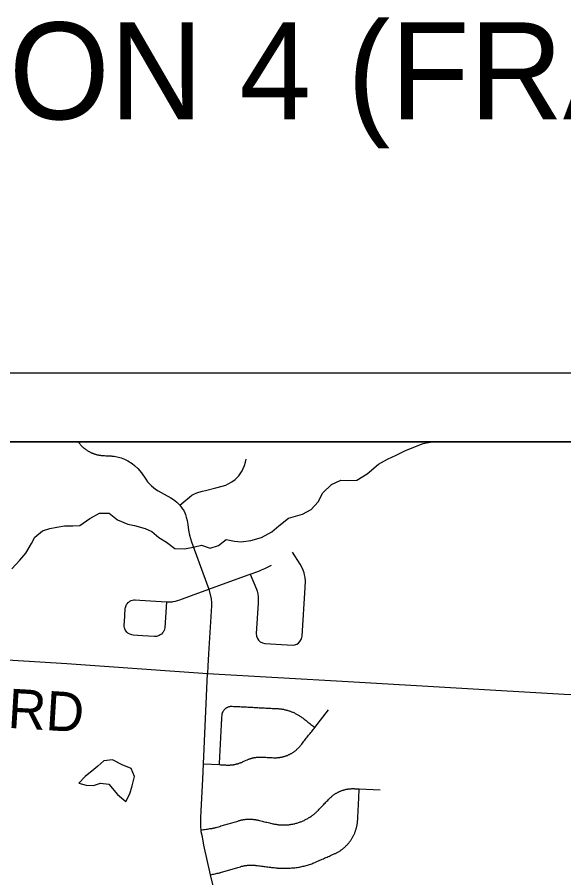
# Model space of a CAD drawing. Extents: x 0 to 34, y 0 to 22.
# Drawn here: x 6.189 to 6.979, y 9.554 to 10.798 of the extents above; entities that cross this region are included whole.
import ezdxf

# ---------------------------------------------------------------- set-up
doc = ezdxf.new("R2010")
doc.units = 0
for name, color, linetype in [('Default', 7, 'Continuous'), ('GM_X_Corporation', 7, 'Continuous'), ('GM_X_Minor_Lake', 7, 'Continuous'), ('GM_X_Minor_River', 7, 'Continuous'), ('GM_X_Township_Road', 7, 'Continuous'), ('GM_X_Township_Road_Text', 7, 'Continuous'), ('SH_Data', 7, 'Continuous')]:
    doc.layers.add(name, color=color, linetype=linetype)

msp = doc.modelspace()

# ---------------------------------------------------------------- linework, layer by layer
at = {"layer": 'GM_X_Corporation'}
for points in [[(10.3182, 6.9963), (10.3182, 10.1841), (3.5182, 10.1841)], [(7.8118, 7.1421), (7.8248, 7.359), (7.8619, 7.9568), (7.8769, 8.1664), (7.8824, 8.2446), (7.9043, 8.6471), (7.9173, 8.8475), (7.9854, 9.7171), (7.9906, 9.8037), (8.012, 10.1113), (8.0168, 10.1841), (3.5182, 10.1841)]]:
    msp.add_lwpolyline(points, dxfattribs=at)
at = {"layer": 'GM_X_Minor_Lake'}
for points in [[(6.3051, 9.7156), (6.2995, 9.7106), (6.287, 9.7007), (6.2776, 9.6908), (6.2882, 9.6882), (6.2988, 9.6874), (6.309, 9.6909), (6.3211, 9.6897), (6.3336, 9.6746), (6.3457, 9.6644)], [(6.3457, 9.6644), (6.3518, 9.6754), (6.3548, 9.6871), (6.3585, 9.7004), (6.3536, 9.7122), (6.3404, 9.7174), (6.3264, 9.7246), (6.3139, 9.7235), (6.3051, 9.7156)]]:
    msp.add_lwpolyline(points, dxfattribs=at)
at = {"layer": 'GM_X_Minor_River'}
msp.add_lwpolyline([(6.1808, 10.0008), (6.1925, 10.0133), (6.2012, 10.0236), (6.2095, 10.0372), (6.214, 10.0467), (6.2253, 10.0558), (6.2359, 10.0592), (6.2462, 10.0612), (6.2571, 10.0627), (6.2692, 10.0627), (6.2791, 10.0635), (6.2938, 10.0734), (6.3078, 10.0813), (6.3218, 10.081), (6.3339, 10.0715), (6.3487, 10.0651), (6.3585, 10.0632), (6.3737, 10.0591), (6.3835, 10.0546), (6.3934, 10.0462), (6.4047, 10.0394), (6.4168, 10.0303), (6.4305, 10.0296), (6.4433, 10.0323), (6.4551, 10.0349), (6.4679, 10.0304), (6.4797, 10.0346), (6.4906, 10.0433), (6.5027, 10.0407), (6.5126, 10.0396), (6.5266, 10.0419), (6.5417, 10.0461), (6.5568, 10.0541), (6.567, 10.0628), (6.5807, 10.0738), (6.5912, 10.0769), (6.6011, 10.0799), (6.6136, 10.0864), (6.6238, 10.0978), (6.6306, 10.1107), (6.643, 10.1228), (6.6566, 10.1289), (6.6676, 10.1285), (6.6797, 10.1289), (6.6945, 10.138), (6.7111, 10.1521), (6.724, 10.1593), (6.7365, 10.165), (6.7493, 10.1715), (6.7622, 10.1768), (6.7758, 10.1821), (6.7879, 10.1841), (6.7881, 10.1841)], dxfattribs=at)
at = {"layer": 'GM_X_Township_Road'}
for points in [[(6.2776, 10.1832), (6.2781, 10.1825), (6.2786, 10.1819), (6.2791, 10.1813), (6.2796, 10.1807), (6.2802, 10.1801), (6.2807, 10.1795), (6.2813, 10.1789), (6.2818, 10.1783), (6.2824, 10.1777), (6.283, 10.1772), (6.2836, 10.1766), (6.2842, 10.1761), (6.2848, 10.1755), (6.2855, 10.175), (6.2861, 10.1745), (6.2868, 10.174), (6.2874, 10.1735), (6.2881, 10.1731), (6.2887, 10.1726), (6.2894, 10.1721), (6.2901, 10.1717), (6.2908, 10.1713), (6.2915, 10.1709), (6.2922, 10.1705), (6.2929, 10.1701), (6.2936, 10.1697), (6.2944, 10.1693), (6.2951, 10.169), (6.2958, 10.1686), (6.2966, 10.1683), (6.2973, 10.168), (6.2981, 10.1677), (6.2988, 10.1674), (6.2996, 10.1671), (6.3004, 10.1668), (6.3011, 10.1666), (6.3019, 10.1664), (6.3027, 10.1661), (6.3035, 10.1659), (6.3043, 10.1657), (6.3051, 10.1655), (6.3059, 10.1654), (6.3067, 10.1652), (6.3075, 10.1651), (6.3083, 10.165), (6.3091, 10.1648), (6.3099, 10.1647), (6.3107, 10.1647), (6.3115, 10.1646), (6.3123, 10.1645), (6.3131, 10.1645), (6.315, 10.1644), (6.3169, 10.1643), (6.3188, 10.1642), (6.3207, 10.1641), (6.3226, 10.164), (6.3236, 10.164), (6.3246, 10.1639), (6.3256, 10.1638), (6.3267, 10.1637), (6.3277, 10.1636), (6.3288, 10.1634), (6.335, 10.1622), (6.3391, 10.161), (6.344, 10.1591), (6.3487, 10.1567), (6.355, 10.1528), (6.3584, 10.1502), (6.3631, 10.146), (6.3685, 10.1395), (6.3746, 10.1305), (6.3772, 10.1267), (6.3828, 10.1205), (6.3886, 10.1159), (6.3923, 10.1136), (6.4014, 10.1086), (6.4106, 10.1036), (6.4146, 10.1011), (6.4195, 10.0973), (6.4238, 10.0928), (6.4273, 10.0881), (6.4299, 10.0841), (6.4319, 10.0792), (6.4332, 10.0753), (6.4344, 10.0705), (6.4352, 10.065), (6.4363, 10.0566), (6.4376, 10.0495), (6.4406, 10.0397), (6.4517, 10.0094), (6.4657, 9.9712), (6.469, 9.9573), (6.4694, 9.9517), (6.4694, 9.9472), (6.4651, 9.8777), (6.4641, 9.8603), (6.4639, 9.8496)], [(6.4238, 10.0928), (6.4295, 10.0978), (6.4376, 10.1045), (6.4414, 10.1071), (6.4443, 10.1087), (6.4484, 10.1106), (6.4515, 10.1117), (6.4568, 10.1132), (6.461, 10.1142), (6.4758, 10.1179), (6.4849, 10.1201), (6.4904, 10.1219), (6.4938, 10.1235), (6.4988, 10.1263), (6.5037, 10.1301), (6.5089, 10.1354), (6.511, 10.138), (6.5139, 10.1425), (6.5156, 10.1458), (6.5173, 10.15), (6.5188, 10.1551), (6.5196, 10.1592)], [(6.5256, 9.993), (6.5345, 9.9714), (6.5354, 9.9684), (6.5364, 9.9644), (6.5371, 9.9597), (6.5371, 9.9509), (6.5343, 9.9072), (6.5346, 9.9036), (6.5359, 9.9002), (6.5375, 9.8978), (6.5402, 9.8953), (6.5431, 9.8936), (6.5468, 9.8927), (6.5872, 9.8902), (6.5902, 9.8907), (6.5928, 9.8917), (6.5955, 9.8935), (6.5974, 9.8956), (6.5997, 9.8996), (6.6005, 9.9034), (6.605, 9.9737), (6.6054, 9.9829), (6.6049, 9.9883), (6.6041, 9.9923), (6.6034, 9.9951), (6.6022, 9.9986), (6.6007, 10.002), (6.5976, 10.0075), (6.5866, 10.0247)], [(6.4044, 9.9531), (6.4029, 9.9304), (6.4022, 9.9154), (6.4017, 9.9136), (6.4011, 9.9118), (6.4006, 9.911), (6.3997, 9.9093), (6.3988, 9.9081), (6.3972, 9.9065), (6.3954, 9.9052), (6.3941, 9.9044), (6.3928, 9.9038), (6.3916, 9.9035), (6.3901, 9.9031), (6.3887, 9.903), (6.3872, 9.9029), (6.3699, 9.9041), (6.3566, 9.9048), (6.3545, 9.9053), (6.3528, 9.9057), (6.3508, 9.9067), (6.3487, 9.908), (6.3473, 9.9094), (6.3461, 9.9107), (6.345, 9.9126), (6.3444, 9.914), (6.3438, 9.9156), (6.3435, 9.9173), (6.3434, 9.9198), (6.3437, 9.9244), (6.345, 9.943), (6.345, 9.9439), (6.3453, 9.9451), (6.3462, 9.9477), (6.3468, 9.949), (6.3477, 9.9503), (6.3491, 9.9519), (6.3501, 9.9528), (6.3515, 9.9538), (6.3534, 9.9548), (6.3556, 9.9556), (6.3575, 9.9559), (6.3592, 9.956), (6.3661, 9.9556), (6.3968, 9.9536), (6.4044, 9.9531), (6.4093, 9.953), (6.4126, 9.9533), (6.4143, 9.9535), (6.4176, 9.9541), (6.4207, 9.9549), (6.4236, 9.9558), (6.4407, 9.9621), (6.4657, 9.9712), (6.5225, 9.9919), (6.5256, 9.993), (6.5379, 9.9975), (6.542, 9.9991), (6.5445, 10.0001), (6.5469, 10.0012), (6.5517, 10.0035), (6.5565, 10.006)], [(5.4689, 9.9123), (5.5957, 9.9046), (5.9632, 9.8822), (6.2604, 9.864), (6.4639, 9.8496), (6.6673, 9.838), (6.9796, 9.8194), (7.0349, 9.8181)], [(6.4798, 9.5107), (6.4683, 9.5585), (6.4585, 9.6014), (6.4564, 9.6135), (6.4548, 9.6205), (6.4545, 9.6233), (6.454, 9.6278), (6.454, 9.6416), (6.4545, 9.6511), (6.4571, 9.6967), (6.458, 9.7189), (6.4639, 9.8496)], [(6.4811, 9.7178), (6.4812, 9.7196), (6.4813, 9.7215), (6.4814, 9.7234), (6.4815, 9.7252), (6.4816, 9.7271), (6.4817, 9.729), (6.4818, 9.7308), (6.4819, 9.7327), (6.482, 9.7346), (6.482, 9.7364), (6.4821, 9.7383), (6.4822, 9.7402), (6.4823, 9.742), (6.4824, 9.7439), (6.4825, 9.7458), (6.4826, 9.7476), (6.4827, 9.7495), (6.4828, 9.7514), (6.4829, 9.7532), (6.483, 9.7551), (6.4831, 9.757), (6.4832, 9.7588), (6.4833, 9.7607), (6.4834, 9.7626), (6.4835, 9.7644), (6.4836, 9.7663), (6.4837, 9.7682), (6.4838, 9.77), (6.4839, 9.7719), (6.484, 9.7738), (6.4841, 9.7756), (6.4842, 9.7775), (6.4843, 9.7794), (6.4844, 9.7812), (6.4845, 9.7831), (6.4846, 9.785), (6.4847, 9.7868), (6.4848, 9.7887), (6.4848, 9.7894), (6.4849, 9.7902), (6.4851, 9.7909), (6.4852, 9.7916), (6.4854, 9.7923), (6.4857, 9.793), (6.486, 9.7937), (6.4863, 9.7943), (6.4866, 9.795), (6.487, 9.7956), (6.4874, 9.7962), (6.4879, 9.7968), (6.4883, 9.7974), (6.4888, 9.7979), (6.4894, 9.7984), (6.4899, 9.7989), (6.4905, 9.7994), (6.4911, 9.7998), (6.4917, 9.8002), (6.4924, 9.8005), (6.493, 9.8009), (6.4937, 9.8011), (6.4944, 9.8014), (6.4951, 9.8016), (6.4958, 9.8018), (6.4965, 9.8019), (6.4973, 9.8021), (6.498, 9.8021), (6.4987, 9.8022), (6.4995, 9.8021), (6.5016, 9.802), (6.5034, 9.8019), (6.5053, 9.8018), (6.5071, 9.8017), (6.509, 9.8017), (6.5108, 9.8016), (6.5127, 9.8015), (6.5146, 9.8014), (6.5164, 9.8013), (6.5183, 9.8012), (6.5201, 9.8011), (6.522, 9.801), (6.5238, 9.8009), (6.5257, 9.8008), (6.5276, 9.8007), (6.5294, 9.8006), (6.5313, 9.8005), (6.5331, 9.8004), (6.535, 9.8003), (6.5368, 9.8002), (6.5387, 9.8001), (6.5405, 9.8), (6.5424, 9.7999), (6.5443, 9.7998), (6.5461, 9.7997), (6.548, 9.7996), (6.5498, 9.7995), (6.5517, 9.7994), (6.5535, 9.7993), (6.5554, 9.7992), (6.5572, 9.7991), (6.5591, 9.799), (6.56, 9.799), (6.561, 9.7989), (6.5628, 9.7988), (6.5647, 9.7987), (6.5658, 9.7987), (6.5669, 9.7986), (6.568, 9.7985), (6.5692, 9.7984), (6.5703, 9.7982), (6.5714, 9.798), (6.5725, 9.7979), (6.5736, 9.7977), (6.5747, 9.7974), (6.5758, 9.7972), (6.5769, 9.7969), (6.578, 9.7967), (6.5791, 9.7964), (6.5802, 9.7961), (6.5813, 9.7957), (6.5823, 9.7954), (6.5834, 9.795), (6.5845, 9.7946), (6.5855, 9.7942), (6.5866, 9.7938), (6.5876, 9.7934), (6.5886, 9.7929), (6.5896, 9.7924), (6.5907, 9.7919), (6.5917, 9.7914), (6.5927, 9.7909), (6.5936, 9.7904), (6.5946, 9.7898), (6.5956, 9.7892), (6.5965, 9.7886), (6.5975, 9.788), (6.5984, 9.7874), (6.5994, 9.7867), (6.6003, 9.7861), (6.6012, 9.7854), (6.6021, 9.7847), (6.6035, 9.7836), (6.6049, 9.7825), (6.6063, 9.7814), (6.6077, 9.7803), (6.6091, 9.7792), (6.6105, 9.7781), (6.6119, 9.777), (6.6133, 9.7759), (6.6147, 9.7748), (6.6161, 9.7737), (6.6175, 9.7726), (6.6189, 9.7715)], [(6.458, 9.7189), (6.4811, 9.7178), (6.4828, 9.7177), (6.4845, 9.7176), (6.4863, 9.7175), (6.488, 9.7174), (6.4897, 9.7173), (6.4915, 9.7172), (6.4923, 9.7172), (6.4931, 9.7172), (6.4939, 9.7172), (6.4947, 9.7172), (6.4955, 9.7172), (6.4963, 9.7172), (6.4971, 9.7173), (6.4979, 9.7173), (6.4988, 9.7174), (6.4996, 9.7175), (6.5004, 9.7176), (6.5012, 9.7177), (6.502, 9.7178), (6.5028, 9.718), (6.5035, 9.7181), (6.5043, 9.7183), (6.5051, 9.7185), (6.5059, 9.7187), (6.5067, 9.7189), (6.5075, 9.7191), (6.5082, 9.7194), (6.509, 9.7196), (6.5098, 9.7199), (6.5105, 9.7202), (6.5113, 9.7205), (6.512, 9.7208), (6.5128, 9.7211), (6.5145, 9.7218), (6.5163, 9.7226), (6.518, 9.7233), (6.5197, 9.7241), (6.5215, 9.7248), (6.5222, 9.7252), (6.523, 9.7255), (6.5237, 9.7257), (6.5245, 9.726), (6.5253, 9.7263), (6.526, 9.7265), (6.5268, 9.7268), (6.5276, 9.727), (6.5284, 9.7272), (6.5291, 9.7274), (6.5299, 9.7276), (6.5307, 9.7278), (6.5315, 9.7279), (6.5323, 9.7281), (6.5331, 9.7282), (6.5339, 9.7283), (6.5347, 9.7284), (6.5355, 9.7285), (6.5363, 9.7286), (6.5371, 9.7286), (6.5379, 9.7287), (6.5387, 9.7287), (6.5396, 9.7288), (6.5404, 9.7288), (6.5412, 9.7287), (6.542, 9.7287), (6.5428, 9.7287), (6.5446, 9.7286), (6.5464, 9.7285), (6.5482, 9.7284), (6.55, 9.7283), (6.5519, 9.7282), (6.5537, 9.7281), (6.5555, 9.728), (6.5573, 9.7279), (6.5591, 9.7278), (6.5599, 9.7278), (6.5608, 9.7278), (6.5616, 9.7278), (6.5624, 9.7278), (6.5632, 9.7278), (6.5641, 9.7278), (6.5649, 9.7279), (6.5657, 9.7279), (6.5665, 9.728), (6.5673, 9.7281), (6.5682, 9.7282), (6.569, 9.7284), (6.5698, 9.7285), (6.5706, 9.7286), (6.5714, 9.7288), (6.5722, 9.729), (6.573, 9.7292), (6.5738, 9.7294), (6.5746, 9.7296), (6.5754, 9.7298), (6.5762, 9.7301), (6.577, 9.7303), (6.5778, 9.7306), (6.5785, 9.7309), (6.5793, 9.7312), (6.5801, 9.7315), (6.5808, 9.7319), (6.5816, 9.7322), (6.5823, 9.7326), (6.583, 9.7329), (6.5838, 9.7333), (6.5845, 9.7337), (6.5852, 9.7341), (6.5859, 9.7345), (6.5866, 9.7349), (6.5873, 9.7354), (6.588, 9.7358), (6.5887, 9.7363), (6.5894, 9.7368), (6.59, 9.7373), (6.5907, 9.7378), (6.5913, 9.7383), (6.592, 9.7388), (6.5926, 9.7394), (6.5932, 9.7399), (6.5938, 9.7405), (6.5944, 9.741), (6.595, 9.7416), (6.5956, 9.7422), (6.5962, 9.7428), (6.5967, 9.7434), (6.5973, 9.744), (6.5978, 9.7446), (6.5983, 9.7453), (6.5989, 9.7459), (6.6, 9.7473), (6.6011, 9.7488), (6.6022, 9.7502), (6.6033, 9.7516), (6.6044, 9.753), (6.6055, 9.7545), (6.6067, 9.7559), (6.6078, 9.7573), (6.6089, 9.7587), (6.61, 9.7602), (6.6111, 9.7616), (6.6122, 9.763), (6.6133, 9.7644), (6.6145, 9.7658), (6.6156, 9.7673), (6.6167, 9.7687), (6.6178, 9.7701), (6.6189, 9.7715), (6.6387, 9.7968)], [(6.4545, 9.6233), (6.4563, 9.6236), (6.4582, 9.6239), (6.46, 9.6241), (6.4619, 9.6244), (6.4637, 9.6247), (6.4656, 9.625), (6.4674, 9.6253), (6.4682, 9.6254), (6.469, 9.6255), (6.4698, 9.6256), (6.4707, 9.6257), (6.4715, 9.6259), (6.4723, 9.626), (6.4731, 9.6262), (6.4738, 9.6264), (6.4746, 9.6266), (6.4754, 9.6268), (6.4762, 9.627), (6.478, 9.6275), (6.4797, 9.628), (6.4815, 9.6286), (6.4833, 9.6291), (6.485, 9.6296), (6.4868, 9.6301), (6.4885, 9.6306), (6.4903, 9.6312), (6.4921, 9.6317), (6.4938, 9.6322), (6.4956, 9.6327), (6.4974, 9.6332), (6.4991, 9.6337), (6.5009, 9.6343), (6.5026, 9.6348), (6.5044, 9.6353), (6.5062, 9.6358), (6.5079, 9.6363), (6.5097, 9.6369), (6.5106, 9.6371), (6.5114, 9.6373), (6.5123, 9.6376), (6.5132, 9.6378), (6.5141, 9.638), (6.515, 9.6381), (6.5159, 9.6383), (6.5167, 9.6384), (6.5176, 9.6386), (6.5185, 9.6387), (6.5194, 9.6388), (6.5203, 9.6388), (6.5212, 9.6389), (6.5221, 9.639), (6.523, 9.639), (6.5239, 9.639), (6.5248, 9.639), (6.5257, 9.639), (6.5267, 9.639), (6.5276, 9.6389), (6.5285, 9.6389), (6.5294, 9.6388), (6.5303, 9.6387), (6.5312, 9.6386), (6.5321, 9.6385), (6.533, 9.6384), (6.5338, 9.6382), (6.5347, 9.6381), (6.5356, 9.6379), (6.5365, 9.6377), (6.5374, 9.6375), (6.5392, 9.637), (6.5409, 9.6366), (6.5427, 9.6362), (6.5445, 9.6357), (6.5462, 9.6353), (6.548, 9.6348), (6.5498, 9.6344), (6.5516, 9.634), (6.5533, 9.6335), (6.5551, 9.6331), (6.5569, 9.6327), (6.5581, 9.6324), (6.5593, 9.6321), (6.5605, 9.6319), (6.5617, 9.6316), (6.5629, 9.6315), (6.5641, 9.6313), (6.5653, 9.6311), (6.5665, 9.631), (6.5677, 9.6309), (6.5689, 9.6308), (6.5702, 9.6307), (6.5714, 9.6306), (6.5726, 9.6306), (6.5738, 9.6306), (6.575, 9.6306), (6.5763, 9.6307), (6.5775, 9.6307), (6.5787, 9.6308), (6.5799, 9.6309), (6.5812, 9.631), (6.5824, 9.6312), (6.5836, 9.6313), (6.5848, 9.6315), (6.586, 9.6317), (6.5872, 9.6319), (6.5884, 9.6322), (6.5896, 9.6324), (6.5908, 9.6327), (6.592, 9.633), (6.5931, 9.6334), (6.5943, 9.6337), (6.5955, 9.6341), (6.5966, 9.6345), (6.5978, 9.6349), (6.5989, 9.6353), (6.6001, 9.6358), (6.6012, 9.6362), (6.6023, 9.6367), (6.6034, 9.6372), (6.6045, 9.6378), (6.6056, 9.6383), (6.6067, 9.6389), (6.6078, 9.6395), (6.6088, 9.6401), (6.6099, 9.6407), (6.6109, 9.6413), (6.612, 9.642), (6.613, 9.6427), (6.614, 9.6434), (6.615, 9.6441), (6.616, 9.6448), (6.6169, 9.6456), (6.6179, 9.6463), (6.6188, 9.6471), (6.6198, 9.6479), (6.6207, 9.6487), (6.6216, 9.6495), (6.6225, 9.6504), (6.6233, 9.6512), (6.6242, 9.6521), (6.6254, 9.6534), (6.6266, 9.6547), (6.6278, 9.6559), (6.6291, 9.6572), (6.6303, 9.6584), (6.6315, 9.6597), (6.6327, 9.661), (6.6339, 9.6622), (6.6351, 9.6635), (6.6364, 9.6648), (6.6376, 9.666), (6.6388, 9.6673), (6.64, 9.6686), (6.6406, 9.6692), (6.6412, 9.6697), (6.6418, 9.6703), (6.6424, 9.6709), (6.643, 9.6714), (6.6436, 9.672), (6.6443, 9.6725), (6.6449, 9.673), (6.6456, 9.6735), (6.6462, 9.674), (6.6469, 9.6745), (6.6476, 9.675), (6.6483, 9.6754), (6.649, 9.6759), (6.6497, 9.6763), (6.6504, 9.6767), (6.6511, 9.6771), (6.6518, 9.6775), (6.6526, 9.6779), (6.6533, 9.6783), (6.654, 9.6786), (6.6548, 9.679), (6.6555, 9.6793), (6.6563, 9.6796), (6.6571, 9.6799), (6.6578, 9.6802), (6.6586, 9.6805), (6.6594, 9.6808), (6.6602, 9.681), (6.661, 9.6812), (6.6618, 9.6815), (6.6626, 9.6817), (6.6634, 9.6819), (6.6642, 9.6821), (6.665, 9.6822), (6.6658, 9.6824), (6.6666, 9.6825), (6.6674, 9.6826), (6.6683, 9.6827), (6.6691, 9.6828), (6.6699, 9.6829), (6.6707, 9.683), (6.6716, 9.683), (6.6724, 9.6831), (6.6732, 9.6831), (6.674, 9.6831), (6.6749, 9.6831), (6.6757, 9.6831), (6.6765, 9.683), (6.6782, 9.683), (6.6799, 9.6829), (6.6815, 9.6828), (6.6832, 9.6827), (6.7135, 9.6812)], [(6.4683, 9.5585), (6.4699, 9.5589), (6.4715, 9.5593), (6.4731, 9.5596), (6.4747, 9.56), (6.4763, 9.5604), (6.4779, 9.5607), (6.4796, 9.5611), (6.4812, 9.5615), (6.4819, 9.5616), (6.4826, 9.5618), (6.4833, 9.562), (6.4841, 9.5622), (6.4858, 9.5627), (6.4875, 9.5632), (6.4892, 9.5637), (6.4909, 9.5642), (6.4926, 9.5647), (6.4943, 9.5652), (6.496, 9.5657), (6.4977, 9.5662), (6.4994, 9.5667), (6.5011, 9.5672), (6.5028, 9.5677), (6.5045, 9.5682), (6.5062, 9.5687), (6.5079, 9.5692), (6.5096, 9.5697), (6.5113, 9.5702), (6.5122, 9.5705), (6.5132, 9.5708), (6.5141, 9.571), (6.5151, 9.5712), (6.516, 9.5714), (6.517, 9.5716), (6.5179, 9.5718), (6.5189, 9.5719), (6.5199, 9.5721), (6.5208, 9.5722), (6.5218, 9.5723), (6.5228, 9.5724), (6.5237, 9.5724), (6.5247, 9.5725), (6.5257, 9.5725), (6.5266, 9.5725), (6.5276, 9.5726), (6.5286, 9.5725), (6.5296, 9.5725), (6.5305, 9.5725), (6.5315, 9.5724), (6.5325, 9.5723), (6.5334, 9.5722), (6.5344, 9.5721), (6.5363, 9.5719), (6.5381, 9.5716), (6.5399, 9.5714), (6.5418, 9.5712), (6.5436, 9.571), (6.5455, 9.5707), (6.5473, 9.5705), (6.5492, 9.5703), (6.551, 9.57), (6.5528, 9.5698), (6.5547, 9.5696), (6.5565, 9.5693), (6.5584, 9.5691), (6.5602, 9.5689), (6.5621, 9.5686), (6.5639, 9.5684), (6.5648, 9.5683), (6.5658, 9.5682), (6.5667, 9.5681), (6.5677, 9.5681), (6.5686, 9.568), (6.5695, 9.568), (6.5705, 9.568), (6.5714, 9.568), (6.5724, 9.568), (6.5739, 9.568), (6.5755, 9.5681), (6.5771, 9.5681), (6.5787, 9.5682), (6.5803, 9.5682), (6.5818, 9.5682), (6.5835, 9.5683), (6.5852, 9.5684), (6.5869, 9.5685), (6.5885, 9.5686), (6.5902, 9.5688), (6.5919, 9.569), (6.5935, 9.5692), (6.5952, 9.5695), (6.5968, 9.5697), (6.5985, 9.5701), (6.6001, 9.5704), (6.6017, 9.5708), (6.6034, 9.5711), (6.605, 9.5716), (6.6066, 9.572), (6.6082, 9.5725), (6.6098, 9.573), (6.6114, 9.5735), (6.613, 9.5741), (6.6146, 9.5746), (6.6161, 9.5752), (6.6177, 9.5759), (6.6192, 9.5765), (6.621, 9.5773), (6.6227, 9.5781), (6.6244, 9.5788), (6.6262, 9.5796), (6.6279, 9.5803), (6.6296, 9.5811), (6.6314, 9.5818), (6.6331, 9.5826), (6.6348, 9.5834), (6.6366, 9.5841), (6.6383, 9.5849), (6.64, 9.5856), (6.6418, 9.5864), (6.6435, 9.5872), (6.6452, 9.5879), (6.647, 9.5887), (6.6479, 9.5891), (6.6488, 9.5895), (6.6497, 9.5899), (6.6505, 9.5904), (6.6514, 9.5908), (6.6523, 9.5913), (6.6531, 9.5918), (6.654, 9.5923), (6.6548, 9.5928), (6.6556, 9.5934), (6.6564, 9.5939), (6.6572, 9.5945), (6.658, 9.5951), (6.6588, 9.5957), (6.6596, 9.5963), (6.6604, 9.5969), (6.6611, 9.5975), (6.6618, 9.5982), (6.6626, 9.5988), (6.6633, 9.5995), (6.664, 9.6002), (6.6647, 9.6009), (6.6654, 9.6016), (6.6661, 9.6023), (6.6667, 9.603), (6.6674, 9.6038), (6.668, 9.6045), (6.6686, 9.6053), (6.6692, 9.6061), (6.6698, 9.6069), (6.6704, 9.6076), (6.671, 9.6084), (6.6715, 9.6093), (6.6721, 9.6101), (6.6726, 9.6109), (6.6731, 9.6118), (6.6736, 9.6126), (6.6741, 9.6135), (6.6745, 9.6143), (6.675, 9.6152), (6.6754, 9.6161), (6.6758, 9.617), (6.6762, 9.6179), (6.6766, 9.6188), (6.677, 9.6197), (6.6774, 9.6206), (6.6777, 9.6215), (6.678, 9.6225), (6.6783, 9.6234), (6.6786, 9.6243), (6.6789, 9.6253), (6.6791, 9.6262), (6.6794, 9.6272), (6.6796, 9.6282), (6.6798, 9.6291), (6.68, 9.6301), (6.6802, 9.631), (6.6804, 9.632), (6.6805, 9.633), (6.6806, 9.634), (6.6807, 9.6349), (6.6808, 9.6359), (6.6809, 9.6369), (6.681, 9.6379), (6.6811, 9.6398), (6.6811, 9.6416), (6.6812, 9.6435), (6.6813, 9.6454), (6.6814, 9.6472), (6.6815, 9.6491), (6.6816, 9.651), (6.6817, 9.6528), (6.6818, 9.6547), (6.6819, 9.6566), (6.682, 9.6584), (6.6821, 9.6603), (6.6822, 9.6622), (6.6823, 9.664), (6.6824, 9.6659), (6.6825, 9.6678), (6.6826, 9.6696), (6.6826, 9.6715), (6.6827, 9.6734), (6.6828, 9.6752), (6.6829, 9.6771), (6.683, 9.679), (6.6831, 9.6808), (6.6832, 9.6827)]]:
    msp.add_lwpolyline(points, dxfattribs=at)
at = {"layer": 'SH_Data'}
for p, q in [((3.4182, 10.2841), (10.4182, 10.2841)), ((3.5182, 10.1841), (10.3182, 10.1841))]:
    msp.add_line(p, q, dxfattribs=at)

# ---------------------------------------------------------------- texts
at = {"layer": 'Default'}
msp.add_text('LOCATION 4 (FRA-71-29.62)', height=0.14, dxfattribs=at).set_placement((5.5007, 10.6505))
at = {"layer": 'GM_X_Township_Road_Text'}
msp.add_text('ORANGE RD', height=0.05682, rotation=356.5707, dxfattribs=at).set_placement((5.8244, 9.792))

doc.saveas('drawing.dxf')
